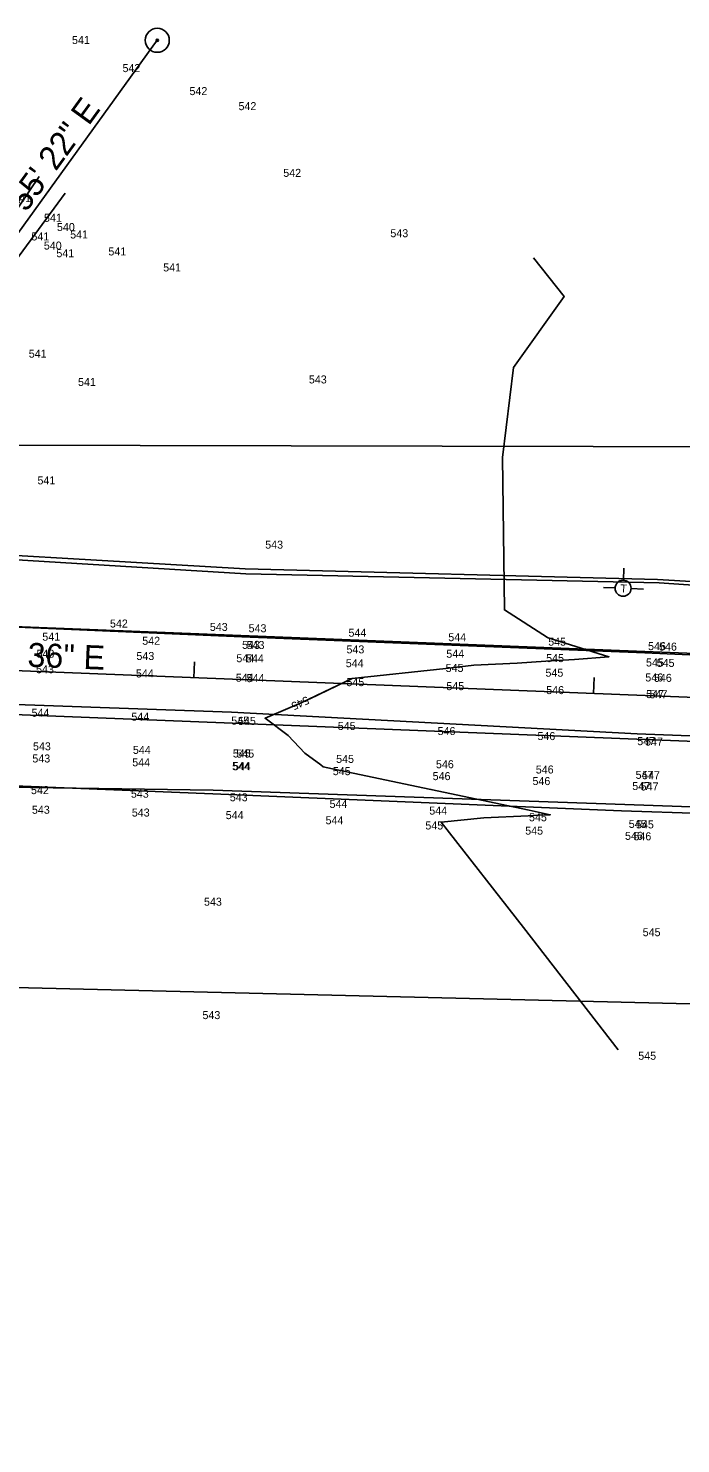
# Model space of a CAD drawing. Extents: x 1787461 to 1970323, y 938412 to 1118748.
# Drawn here: x 1968936.6 to 1969099.8, y 1117714.7 to 1118068.5 of the extents above; entities that cross this region are included whole.
import ezdxf

# ---------------------------------------------------------------- set-up
doc = ezdxf.new("R2010")
doc.units = 0
for name, color, linetype in [('Default', 7, 'Continuous'), ('HHA ADDITIONAL XSs', 7, 'Continuous'), ('RD_EX_DV_Prop', 7, 'Continuous'), ('RD_EX_Fence_Other', 7, 'Continuous'), ('RD_EX_H2O', 7, 'Continuous'), ('RD_EX_Road', 7, 'Continuous'), ('RD_EX_UT', 7, 'Continuous'), ('RD_EX_VEG', 7, 'Continuous'), ('RD_HC_CL', 7, 'Continuous'), ('RD_HC_Data', 7, 'Continuous'), ('RD_HC_Data_Tic', 7, 'Continuous'), ('RD_PD_Final_TrvlWay', 7, 'Continuous'), ('RD_SMD_Locator', 7, 'Continuous')]:
    doc.layers.add(name, color=color, linetype=linetype)

msp = doc.modelspace()

# ---------------------------------------------------------------- linework, layer by layer
at = {"layer": 'Default'}
for points in [[(1969062.95, 1118011.17), (1969070.6, 1118001.47), (1969057.96, 1117983.73), (1969055.19, 1117961.21), (1969055.7, 1117923.16), (1969066.45, 1117916.22), (1969066.63, 1117916.17), (1969081.83, 1117911.42), (1969073.25, 1117910.71), (1969066.04, 1117910.31), (1969058.87, 1117909.8), (1969048.04, 1117909.3), (1969041.03, 1117908.5), (1969017.63, 1117906.03), (1969016.95, 1117905.69), (1969016.03, 1117905.27), (1969004.89, 1117899.92), (1968995.84, 1117896.06), (1969001.6, 1117891.75), (1969005.82, 1117887.32), (1969009.78, 1117884.39), (1969010.37, 1117883.96), (1969012.74, 1117883.46), (1969014.74, 1117883.04), (1969037.31, 1117878.27), (1969058.26, 1117873.84), (1969061.91, 1117873.07), (1969067.15, 1117871.96), (1969064.12, 1117871.87), (1969061.66, 1117871.69), (1969050.51, 1117871.14), (1969039.89, 1117870.06), (1969060.45, 1117843.74), (1969084.15, 1117813.17)], [(1969062.95, 1118011.17), (1969070.6, 1118001.47), (1969057.96, 1117983.73), (1969055.19, 1117961.21), (1969055.7, 1117923.16), (1969066.45, 1117916.22), (1969066.63, 1117916.17), (1969081.83, 1117911.42), (1969073.25, 1117910.71), (1969066.04, 1117910.31), (1969058.87, 1117909.8), (1969048.04, 1117909.3), (1969041.03, 1117908.5), (1969017.63, 1117906.03), (1969016.95, 1117905.69), (1969016.03, 1117905.27), (1969007.02, 1117900.95)], [(1969062.95, 1118011.17), (1969070.6, 1118001.47), (1969057.96, 1117983.73), (1969055.19, 1117961.21), (1969055.7, 1117923.16), (1969066.45, 1117916.22), (1969066.63, 1117916.17), (1969081.83, 1117911.42), (1969073.25, 1117910.71), (1969066.04, 1117910.31), (1969058.87, 1117909.8), (1969048.04, 1117909.3), (1969041.03, 1117908.5), (1969017.63, 1117906.03), (1969016.95, 1117905.69), (1969016.03, 1117905.27), (1969007.02, 1117900.95)], [(1969062.95, 1118011.17), (1969070.6, 1118001.47), (1969057.96, 1117983.73), (1969055.19, 1117961.21), (1969055.7, 1117923.16), (1969066.45, 1117916.22), (1969066.63, 1117916.17), (1969081.83, 1117911.42), (1969073.25, 1117910.71), (1969066.04, 1117910.31), (1969058.87, 1117909.8), (1969048.04, 1117909.3), (1969041.03, 1117908.5), (1969017.63, 1117906.03), (1969016.95, 1117905.69), (1969016.03, 1117905.27), (1969007.02, 1117900.95)], [(1969062.95, 1118011.17), (1969070.6, 1118001.47), (1969057.96, 1117983.73), (1969055.19, 1117961.21), (1969055.7, 1117923.16), (1969066.45, 1117916.22), (1969066.63, 1117916.17), (1969081.83, 1117911.42), (1969073.25, 1117910.71), (1969066.04, 1117910.31), (1969058.87, 1117909.8), (1969048.04, 1117909.3), (1969041.03, 1117908.5), (1969017.63, 1117906.03), (1969016.95, 1117905.69), (1969016.03, 1117905.27), (1969007.02, 1117900.95)], [(1969062.95, 1118011.17), (1969070.6, 1118001.47), (1969057.96, 1117983.73), (1969055.19, 1117961.21), (1969055.7, 1117923.16), (1969066.45, 1117916.22), (1969066.63, 1117916.17), (1969081.83, 1117911.42), (1969073.25, 1117910.71), (1969066.04, 1117910.31), (1969058.87, 1117909.8), (1969048.04, 1117909.3), (1969041.03, 1117908.5), (1969017.63, 1117906.03), (1969016.95, 1117905.69), (1969016.03, 1117905.27), (1969007.02, 1117900.95)], [(1969062.95, 1118011.17), (1969070.6, 1118001.47), (1969057.96, 1117983.73), (1969055.19, 1117961.21), (1969055.7, 1117923.16), (1969066.45, 1117916.22), (1969066.63, 1117916.17), (1969081.83, 1117911.42), (1969073.25, 1117910.71), (1969066.04, 1117910.31), (1969058.87, 1117909.8), (1969048.04, 1117909.3), (1969041.03, 1117908.5), (1969017.63, 1117906.03), (1969016.95, 1117905.69), (1969016.03, 1117905.27), (1969007.02, 1117900.95)], [(1969001.54, 1117898.5), (1968995.84, 1117896.06), (1969001.6, 1117891.75), (1969005.82, 1117887.32), (1969009.78, 1117884.39), (1969010.37, 1117883.96), (1969012.74, 1117883.46), (1969014.74, 1117883.04), (1969037.31, 1117878.27), (1969058.26, 1117873.84), (1969061.91, 1117873.07), (1969067.15, 1117871.96), (1969064.12, 1117871.87), (1969061.66, 1117871.69), (1969050.51, 1117871.14), (1969039.89, 1117870.06), (1969060.45, 1117843.74), (1969084.15, 1117813.17)], [(1969001.54, 1117898.5), (1968995.84, 1117896.06), (1969001.6, 1117891.75), (1969005.82, 1117887.32), (1969009.78, 1117884.39), (1969010.37, 1117883.96), (1969012.74, 1117883.46), (1969014.74, 1117883.04), (1969037.31, 1117878.27), (1969058.26, 1117873.84), (1969061.91, 1117873.07), (1969067.15, 1117871.96), (1969064.12, 1117871.87), (1969061.66, 1117871.69), (1969050.51, 1117871.14), (1969039.89, 1117870.06), (1969060.45, 1117843.74), (1969084.15, 1117813.17)], [(1969001.54, 1117898.5), (1968995.84, 1117896.06), (1969001.6, 1117891.75), (1969005.82, 1117887.32), (1969009.78, 1117884.39), (1969010.37, 1117883.96), (1969012.74, 1117883.46), (1969014.74, 1117883.04), (1969037.31, 1117878.27), (1969058.26, 1117873.84), (1969061.91, 1117873.07), (1969067.15, 1117871.96), (1969064.12, 1117871.87), (1969061.66, 1117871.69), (1969050.51, 1117871.14), (1969039.89, 1117870.06), (1969060.45, 1117843.74), (1969084.15, 1117813.17)], [(1969001.54, 1117898.5), (1968995.84, 1117896.06), (1969001.6, 1117891.75), (1969005.82, 1117887.32), (1969009.78, 1117884.39), (1969010.37, 1117883.96), (1969012.74, 1117883.46), (1969014.74, 1117883.04), (1969037.31, 1117878.27), (1969058.26, 1117873.84), (1969061.91, 1117873.07), (1969067.15, 1117871.96), (1969064.12, 1117871.87), (1969061.66, 1117871.69), (1969050.51, 1117871.14), (1969039.89, 1117870.06), (1969060.45, 1117843.74), (1969084.15, 1117813.17)], [(1969001.54, 1117898.5), (1968995.84, 1117896.06), (1969001.6, 1117891.75), (1969005.82, 1117887.32), (1969009.78, 1117884.39), (1969010.37, 1117883.96), (1969012.74, 1117883.46), (1969014.74, 1117883.04), (1969037.31, 1117878.27), (1969058.26, 1117873.84), (1969061.91, 1117873.07), (1969067.15, 1117871.96), (1969064.12, 1117871.87), (1969061.66, 1117871.69), (1969050.51, 1117871.14), (1969039.89, 1117870.06), (1969060.45, 1117843.74), (1969084.15, 1117813.17)], [(1969001.54, 1117898.5), (1968995.84, 1117896.06), (1969001.6, 1117891.75), (1969005.82, 1117887.32), (1969009.78, 1117884.39), (1969010.37, 1117883.96), (1969012.74, 1117883.46), (1969014.74, 1117883.04), (1969037.31, 1117878.27), (1969058.26, 1117873.84), (1969061.91, 1117873.07), (1969067.15, 1117871.96), (1969064.12, 1117871.87), (1969061.66, 1117871.69), (1969050.51, 1117871.14), (1969039.89, 1117870.06), (1969060.45, 1117843.74), (1969084.15, 1117813.17)]]:
    msp.add_lwpolyline(points, dxfattribs=at)
at = {"layer": 'HHA ADDITIONAL XSs'}
for points in [[(1969266.55, 1117963.61), (1967907.56, 1117966.55), (1967403.98, 1117771.66), (1967075.57, 1117641.84)], [(1969308.89, 1117819.66), (1967912.94, 1117853.44), (1967442.55, 1117653.93), (1967107.32, 1117508.48)]]:
    msp.add_lwpolyline(points, dxfattribs=at)
at = {"layer": 'RD_EX_DV_Prop'}
msp.add_line((1968370.12, 1117930.34), (1969277.79, 1117894.3), dxfattribs=at)
at = {"layer": 'RD_EX_Fence_Other'}
for points in [[(1968536.3, 1117952.23), (1968681.42, 1117947.34), (1968783.46, 1117943.44), (1968890.68, 1117939.26), (1968990.9, 1117933.42), (1969093.99, 1117930.77), (1969190.99, 1117925.01), (1969281.24, 1117923.59)], [(1968579.94, 1117894.82), (1968678.66, 1117889.64), (1968779.4, 1117886.8), (1968885.65, 1117881.12), (1968982.76, 1117877.17), (1969084.96, 1117872.96), (1969186.26, 1117869.55), (1969289.22, 1117863.98)]]:
    msp.add_lwpolyline(points, dxfattribs=at)
at = {"layer": 'RD_EX_H2O'}
for points in [[(1968871.21, 1117935.49), (1968884.56, 1117957.36), (1968903.71, 1117980.96), (1968922.18, 1118006.14), (1968939.33, 1118031.51)], [(1968880.9, 1117932.65), (1968895.62, 1117952.72), (1968911.6, 1117976.52), (1968927.62, 1118002.53), (1968945.88, 1118027.35)]]:
    msp.add_lwpolyline(points, dxfattribs=at)
at = {"layer": 'RD_EX_Road'}
for points in [[(1968529.31, 1117935.06), (1968680.74, 1117928.37), (1968782, 1117924.72), (1968887.41, 1117920.79), (1968989.99, 1117916.45), (1969090.76, 1117912.42), (1969189.86, 1117908.01), (1969282.04, 1117904.78)], [(1968526.59, 1117915.77), (1968679.57, 1117908.43), (1968780.48, 1117904.73), (1968886.63, 1117901.2), (1968987.42, 1117897.59), (1969088.87, 1117892.19), (1969188.08, 1117888.4), (1969281.71, 1117884.78)]]:
    msp.add_lwpolyline(points, dxfattribs=at)
at = {"layer": 'RD_EX_UT'}
for p, q in [((1969085.56, 1117933.62), (1969085.44, 1117930.55)), ((1969080.44, 1117928.76), (1969083.36, 1117928.65)), ((1969087.36, 1117928.49), (1969090.43, 1117928.37))]:
    msp.add_line(p, q, dxfattribs=at)
msp.add_circle((1969085.36, 1117928.55), 2, dxfattribs=at)
at = {"layer": 'RD_EX_VEG'}
for points in [[(1968535.19, 1117951.62), (1968681.64, 1117944.89), (1968783.26, 1117941.54), (1968890.11, 1117938.32), (1968991.04, 1117932.18), (1969094.36, 1117929.93), (1969190.81, 1117923.37), (1969281.69, 1117922.69)], [(1968580.4, 1117892.39), (1968677.7, 1117886.58), (1968780.39, 1117884.76), (1968885.66, 1117879.53), (1968982.9, 1117878.1), (1969085.82, 1117874.51), (1969187.45, 1117870.95), (1969289.3, 1117866.04)]]:
    msp.add_lwpolyline(points, dxfattribs=at)
at = {"layer": 'RD_HC_CL'}
for p, q in [((1968856.94, 1117911.01), (1968968.89, 1118065.53)), ((1968119.1, 1117940.3), (1969277.79, 1117894.3))]:
    msp.add_line(p, q, dxfattribs=at)
at = {"layer": 'RD_HC_Data'}
for radius in [3, 0.282]:
    msp.add_circle((1968968.89, 1118065.53), radius, dxfattribs=at)
at = {"layer": 'RD_HC_Data_Tic'}
for p, q in [((1968978.02, 1117906.2), (1968978.18, 1117910.2)), ((1969077.94, 1117902.24), (1969078.1, 1117906.24))]:
    msp.add_line(p, q, dxfattribs=at)
at = {"layer": 'RD_PD_Final_TrvlWay'}
for p, q in [((1968478.85, 1117937.03), (1969278.22, 1117905.3)), ((1968477.98, 1117915.05), (1969277.35, 1117883.31))]:
    msp.add_line(p, q, dxfattribs=at)
at = {"layer": 'RD_SMD_Locator'}
msp.add_circle((1968968.89, 1118065.53), 0.001, dxfattribs=at)

# ---------------------------------------------------------------- texts
at = {"layer": 'Default'}
for s, p in [('541', (1968947.56, 1118064.6)), ('542', (1968960.19, 1118057.58)), ('542', (1968976.93, 1118051.83)), ('542', (1968989.19, 1118048.07)), ('542', (1969000.39, 1118031.39)), ('541', (1968932.86, 1118025.08)), ('541', (1968940.56, 1118020.16)), ('540', (1968943.8, 1118017.85)), ('541', (1968937.41, 1118015.5)), ('541', (1968947.1, 1118015.99)), ('543', (1969027.17, 1118016.3)), ('540', (1968940.52, 1118013.22)), ('541', (1968943.66, 1118011.31)), ('541', (1968956.66, 1118011.75)), ('541', (1968970.36, 1118007.75)), ('541', (1968936.75, 1117986.2)), ('541', (1968949.07, 1117979.12)), ('543', (1969006.79, 1117979.76)), ('541', (1968938.93, 1117954.53)), ('543', (1968995.87, 1117938.46)), ('542', (1968957.06, 1117918.74)), ('541', (1968940.14, 1117915.45)), ('542', (1968965.12, 1117914.43)), ('543', (1968982.03, 1117917.89)), ('543', (1968991.72, 1117917.56)), ('544', (1969016.69, 1117916.44)), ('544', (1969041.66, 1117915.33)), ('543', (1968938.68, 1117911.2)), ('543', (1968990.09, 1117913.41)), ('543', (1968991.22, 1117913.37)), ('543', (1969016.19, 1117912.28)), ('544', (1969041.16, 1117911.19)), ('545', (1969066.63, 1117914.21)), ('546', (1969091.6, 1117913.09)), ('546', (1969094.35, 1117912.97)), ('543', (1968963.67, 1117910.63)), ('544', (1968988.66, 1117910.07)), ('544', (1968991.06, 1117910.02)), ('544', (1969016.02, 1117908.83)), ('545', (1969040.99, 1117907.64)), ('545', (1969066.12, 1117910.1)), ('545', (1969091.09, 1117909.01)), ('545', (1969093.76, 1117908.9)), ('543', (1968938.58, 1117907.32)), ('544', (1968963.55, 1117906.26)), ('544', (1968988.52, 1117905.2)), ('544', (1968991.22, 1117905.09)), ('545', (1969016.19, 1117904.09)), ('545', (1969065.95, 1117906.45)), ('546', (1969090.92, 1117905.26)), ('546', (1969093.07, 1117905.16)), ('545', (1969041.17, 1117903.09)), ('546', (1969066.14, 1117902.1)), ('547', (1969091.11, 1117901.1)), ('547', (1969091.98, 1117901.06)), ('544', (1968937.44, 1117896.43)), ('544', (1968962.41, 1117895.45)), ('545', (1968987.39, 1117894.47)), ('545', (1968989.06, 1117894.4)), ('545', (1969014.02, 1117893.14)), ('546', (1969038.98, 1117891.87)), ('546', (1969063.94, 1117890.61)), ('543', (1968937.81, 1117888.05)), ('544', (1968962.79, 1117887.16)), ('545', (1968987.77, 1117886.26)), ('545', (1968988.65, 1117886.23)), ('547', (1969088.91, 1117889.34)), ('547', (1969090.87, 1117889.24)), ('543', (1968937.65, 1117885.01)), ('544', (1968962.63, 1117884.05)), ('544', (1968987.6, 1117883.09)), ('544', (1968987.81, 1117883.08)), ('545', (1969013.61, 1117884.9)), ('546', (1969038.57, 1117883.57)), ('545', (1969012.77, 1117881.84)), ('546', (1969037.74, 1117880.6)), ('546', (1969062.7, 1117879.36)), ('546', (1969063.53, 1117882.25)), ('547', (1969088.49, 1117880.92)), ('547', (1969090.1, 1117880.83)), ('542', (1968937.31, 1117877.1)), ('543', (1968962.29, 1117876.2)), ('547', (1969087.66, 1117878.12)), ('547', (1969089.75, 1117878.01)), ('543', (1968937.54, 1117872.19)), ('543', (1968987.02, 1117875.31)), ('544', (1969011.96, 1117873.64)), ('543', (1968962.52, 1117871.5)), ('544', (1968986, 1117870.85)), ('544', (1969010.96, 1117869.56)), ('544', (1969036.9, 1117871.98)), ('545', (1969061.84, 1117870.31)), ('545', (1969086.77, 1117868.65)), ('545', (1969088.58, 1117868.53)), ('545', (1969035.92, 1117868.26)), ('545', (1969060.88, 1117866.97)), ('546', (1969085.84, 1117865.67)), ('546', (1969087.95, 1117865.56)), ('543', (1968980.57, 1117849.21)), ('545', (1969090.26, 1117841.58)), ('543', (1968980.18, 1117820.86)), ('545', (1969089.15, 1117810.7))]:
    msp.add_text(s, height=2, dxfattribs=at).set_placement(p)
msp.add_text('545', height=2, rotation=204.1087, dxfattribs=at).set_placement((1969006.27, 1117901.65))
msp.add_text('545', height=2, rotation=204.1087, dxfattribs=at).set_placement((1969006.27, 1117901.65))
msp.add_text('545', height=2, rotation=204.1087, dxfattribs=at).set_placement((1969006.27, 1117901.65))
msp.add_text('545', height=2, rotation=204.1087, dxfattribs=at).set_placement((1969006.27, 1117901.65))
msp.add_text('545', height=2, rotation=204.1087, dxfattribs=at).set_placement((1969006.27, 1117901.65))
msp.add_text('545', height=2, rotation=204.1087, dxfattribs=at).set_placement((1969006.27, 1117901.65))
at = {"layer": 'RD_EX_UT'}
msp.add_text('T', height=2, rotation=357.7266, dxfattribs=at).set_placement((1969084.65, 1117927.53))
at = {"layer": 'RD_HC_Data'}
for s, rotation, p in [('N 35%%d 55\' 22" E', 54.0772, (1968922.95, 1118004.24)), ('S 87%%D 43\' 36" E', 357.7266, (1968901.76, 1117910.33))]:
    msp.add_text(s, height=6, rotation=rotation, dxfattribs=at).set_placement(p)

doc.saveas('drawing.dxf')
